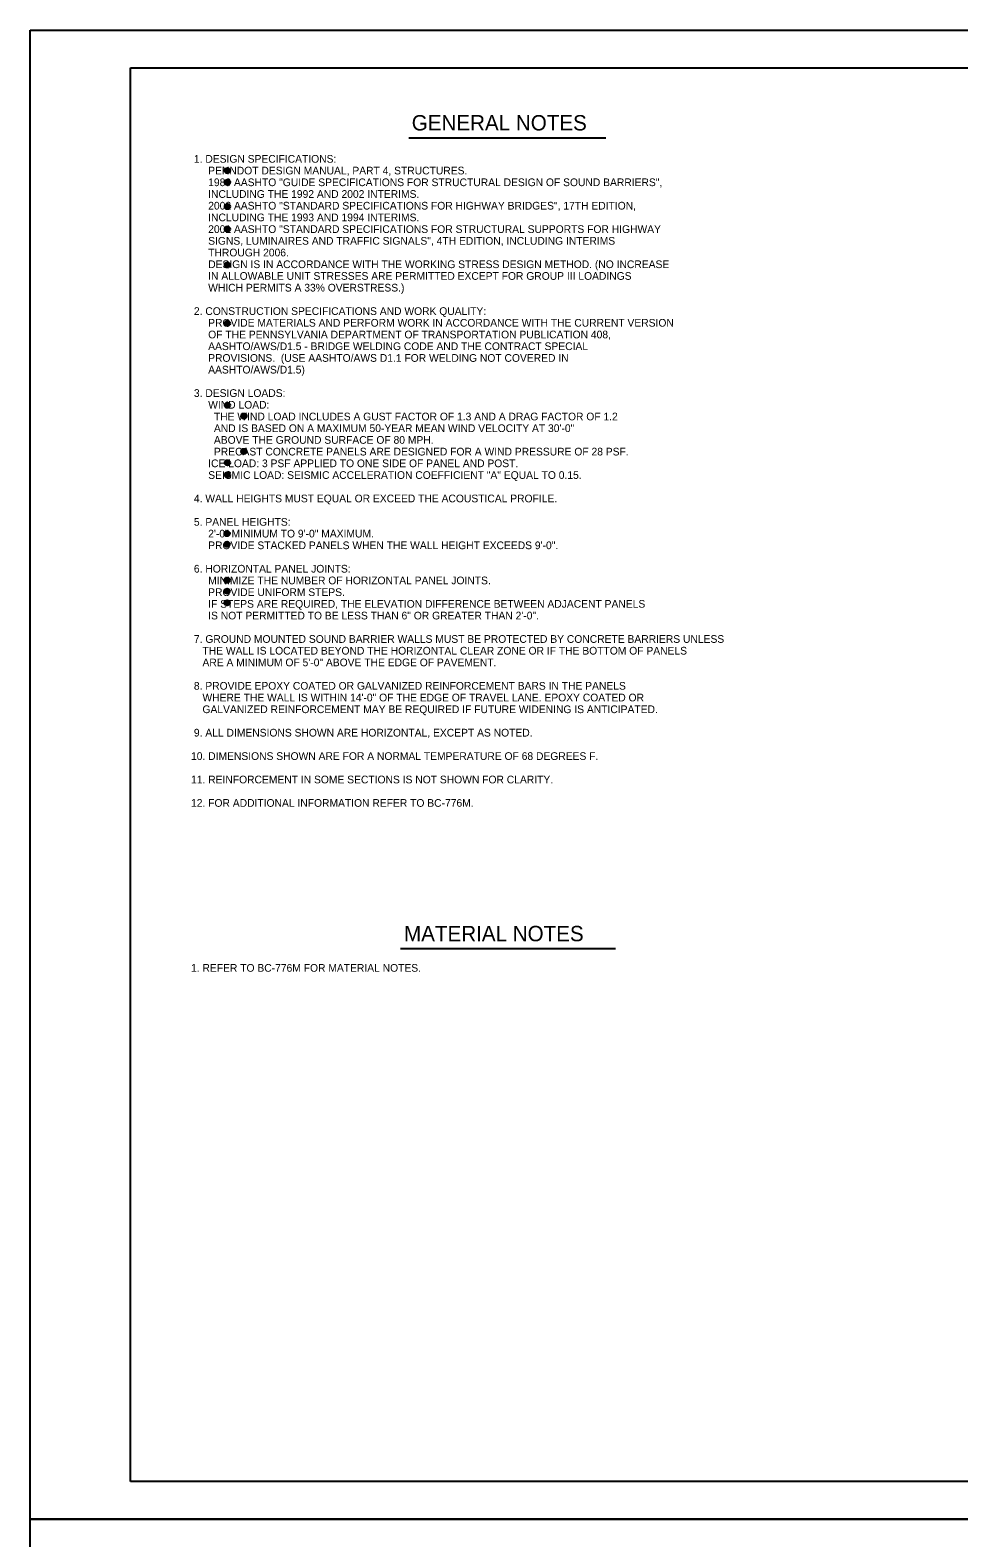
# Model space of a CAD drawing. Extents: x 3761 to 5458, y -616 to 1166.
# Drawn here: x 3761 to 4132, y 564 to 1166 of the extents above; entities that cross this region are included whole.
import ezdxf

# ---------------------------------------------------------------- set-up
doc = ezdxf.new("R2010")
doc.units = 0
for name, color, linetype in [('1', 7, 'Continuous'), ('2', 7, 'Continuous'), ('PLT-BNDY', 7, 'Continuous')]:
    doc.layers.add(name, color=color, linetype=linetype)

msp = doc.modelspace()

# ---------------------------------------------------------------- linework, layer by layer
at = {"layer": '1'}
for p, q in [((3912.43, 1122.78), (3991, 1122.78)), ((3909.14, 799.31), (3994.95, 799.31))]:
    msp.add_line(p, q, dxfattribs=at)
for centre, radius in [((3840.03, 1109.66), 1.07), ((3840.03, 1109.66), 0.8), ((3840.03, 1109.66), 0.533), ((3840.03, 1109.66), 0.267), ((3840.03, 1104.99), 1.07), ((3840.03, 1104.99), 0.8), ((3840.03, 1104.99), 0.533), ((3840.03, 1104.99), 0.267), ((3840.03, 1095.31), 1.07), ((3840.03, 1095.31), 0.8), ((3840.03, 1095.31), 0.533), ((3840.03, 1095.31), 0.267), ((3840.03, 1086.31), 1.07), ((3840.03, 1086.31), 0.8), ((3840.03, 1086.31), 0.533), ((3840.03, 1086.31), 0.267), ((3840.03, 1072.02), 1.07), ((3840.03, 1072.02), 0.8), ((3840.03, 1072.02), 0.533), ((3840.03, 1072.02), 0.267), ((3840.03, 1048.69), 1.07), ((3840.03, 1048.69), 0.8), ((3840.03, 1048.69), 0.533), ((3840.03, 1048.69), 0.267), ((3840.03, 1016.04), 1.07), ((3840.03, 1016.04), 0.8), ((3840.03, 1016.04), 0.533), ((3840.03, 1016.04), 0.267), ((3846.61, 1011.75), 1.07), ((3846.61, 1011.75), 0.8), ((3846.61, 1011.75), 0.533), ((3846.61, 1011.75), 0.267), ((3846.61, 997.62), 1.07), ((3840.03, 993.11), 1.07), ((3840.03, 993.11), 0.8), ((3840.03, 993.11), 0.533), ((3840.03, 993.11), 0.267), ((3846.61, 997.62), 0.8), ((3846.61, 997.62), 0.533), ((3846.61, 997.62), 0.267), ((3840.03, 988.26), 1.07), ((3840.03, 988.26), 0.8), ((3840.03, 988.26), 0.533), ((3840.03, 988.26), 0.267), ((3839.91, 964.82), 1.07), ((3839.91, 964.82), 0.8), ((3839.91, 964.82), 0.533), ((3839.91, 964.82), 0.267), ((3839.91, 960.59), 1.07), ((3839.91, 960.59), 0.8), ((3839.91, 960.59), 0.533), ((3839.91, 960.59), 0.267), ((3839.91, 946.25), 1.07), ((3839.91, 946.25), 0.8), ((3839.91, 946.25), 0.533), ((3839.91, 946.25), 0.267), ((3839.91, 941.88), 1.07), ((3839.91, 941.88), 0.8), ((3839.91, 941.88), 0.533), ((3839.91, 941.88), 0.267), ((3839.91, 937.21), 1.07), ((3839.91, 937.21), 0.8), ((3839.91, 937.21), 0.533), ((3839.91, 937.21), 0.267)]:
    msp.add_circle(centre, radius, dxfattribs=at)
at = {"layer": '2'}
for p, q in [((3801.34, 586.69), (3801.34, 1150.69)), ((3801.34, 1150.69), (4587.34, 1150.69)), ((4587.34, 586.69), (3801.34, 586.69))]:
    msp.add_line(p, q, dxfattribs=at)
at = {"layer": 'PLT-BNDY'}
for points in [[(3761.34, 1165.69), (4602.34, 1165.69), (4602.34, 571.69), (3761.34, 571.69)], [(3761.34, 571.69), (4602.34, 571.69), (4602.34, -22.31), (3761.34, -22.31)]]:
    msp.add_lwpolyline(points, close=True, dxfattribs=at)

# ---------------------------------------------------------------- texts
at = {"layer": '1'}
for s, height, p in [('GENERAL NOTES', 6.144, (3913.59, 1125.67)), (' 1. DESIGN SPECIFICATIONS:', 3.072, (3825.53, 1112.81)), ('      PENNDOT DESIGN MANUAL, PART 4, STRUCTURES.', 3.072, (3825.53, 1108.14)), ('      1989 AASHTO "GUIDE SPECIFICATIONS FOR STRUCTURAL DESIGN OF SOUND BARRIERS",', 3.072, (3825.53, 1103.46)), ('      INCLUDING THE 1992 AND 2002 INTERIMS.', 3.072, (3825.53, 1098.79)), ('      2002 AASHTO "STANDARD SPECIFICATIONS FOR HIGHWAY BRIDGES", 17TH EDITION, ', 3.072, (3825.53, 1094.12)), ('      INCLUDING THE 1993 AND 1994 INTERIMS.', 3.072, (3825.53, 1089.45)), ('      SIGNS, LUMINAIRES AND TRAFFIC SIGNALS", 4TH EDITION, INCLUDING INTERIMS', 3.072, (3825.53, 1080.1)), ('      2001 AASHTO "STANDARD SPECIFICATIONS FOR STRUCTURAL SUPPORTS FOR HIGHWAY', 3.072, (3825.53, 1084.78)), ('      THROUGH 2006.', 3.072, (3825.53, 1075.43)), ('      DESIGN IS IN ACCORDANCE WITH THE WORKING STRESS DESIGN METHOD. (NO INCREASE', 3.072, (3825.53, 1070.76)), ('      IN ALLOWABLE UNIT STRESSES ARE PERMITTED EXCEPT FOR GROUP III LOADINGS', 3.072, (3825.53, 1066.09)), ('      WHICH PERMITS A 33% OVERSTRESS.)', 3.072, (3825.53, 1061.42)), (' 2. CONSTRUCTION SPECIFICATIONS AND WORK QUALITY:', 3.072, (3825.53, 1052.07)), ('      PROVIDE MATERIALS AND PERFORM WORK IN ACCORDANCE WITH THE CURRENT VERSION', 3.072, (3825.53, 1047.4)), ('      AASHTO/AWS/D1.5 - BRIDGE WELDING CODE AND THE CONTRACT SPECIAL', 3.072, (3825.53, 1038.06)), ('      OF THE PENNSYLVANIA DEPARTMENT OF TRANSPORTATION PUBLICATION 408,', 3.072, (3825.53, 1042.73)), ('      PROVISIONS.  (USE AASHTO/AWS D1.1 FOR WELDING NOT COVERED IN ', 3.072, (3825.53, 1033.38)), ('      AASHTO/AWS/D1.5)', 3.072, (3825.53, 1028.71)), (' 3. DESIGN LOADS:', 3.072, (3825.53, 1019.37)), ('      WIND LOAD:', 3.072, (3825.53, 1014.7)), ('        THE WIND LOAD INCLUDES A GUST FACTOR OF 1.3 AND A DRAG FACTOR OF 1.2', 3.072, (3825.53, 1010.02)), ('        AND IS BASED ON A MAXIMUM 50-YEAR MEAN WIND VELOCITY AT 30\'-0"', 3.072, (3825.53, 1005.35)), ('        ABOVE THE GROUND SURFACE OF 80 MPH.', 3.072, (3825.53, 1000.68)), ('        PRECAST CONCRETE PANELS ARE DESIGNED FOR A WIND PRESSURE OF 28 PSF.', 3.072, (3825.53, 996.01)), ('      ICE LOAD: 3 PSF APPLIED TO ONE SIDE OF PANEL AND POST.', 3.072, (3825.53, 991.34)), ('      SEISMIC LOAD: SEISMIC ACCELERATION COEFFICIENT "A" EQUAL TO 0.15.', 3.072, (3825.53, 986.66)), (' 4. WALL HEIGHTS MUST EQUAL OR EXCEED THE ACOUSTICAL PROFILE.', 3.072, (3825.53, 977.32)), (' 5. PANEL HEIGHTS:', 3.072, (3825.53, 967.98)), ('      2\'-0" MINIMUM TO 9\'-0" MAXIMUM.', 3.072, (3825.53, 963.3)), ('      PROVIDE STACKED PANELS WHEN THE WALL HEIGHT EXCEEDS 9\'-0".', 3.072, (3825.53, 958.63)), (' 6. HORIZONTAL PANEL JOINTS:', 3.072, (3825.53, 949.29)), ('      MINIMIZE THE NUMBER OF HORIZONTAL PANEL JOINTS.', 3.072, (3825.53, 944.62)), ('      PROVIDE UNIFORM STEPS.', 3.072, (3825.53, 939.94)), ('      IF STEPS ARE REQUIRED, THE ELEVATION DIFFERENCE BETWEEN ADJACENT PANELS', 3.072, (3825.53, 935.27)), ('      IS NOT PERMITTED TO BE LESS THAN 6" OR GREATER THAN 2\'-0".', 3.072, (3825.53, 930.6)), (' 7. GROUND MOUNTED SOUND BARRIER WALLS MUST BE PROTECTED BY CONCRETE BARRIERS UNLESS', 3.072, (3825.53, 921.26)), ('    ARE A MINIMUM OF 5\'-0" ABOVE THE EDGE OF PAVEMENT.', 3.072, (3825.53, 911.91)), ('    THE WALL IS LOCATED BEYOND THE HORIZONTAL CLEAR ZONE OR IF THE BOTTOM OF PANELS', 3.072, (3825.53, 916.58)), (' 8. PROVIDE EPOXY COATED OR GALVANIZED REINFORCEMENT BARS IN THE PANELS', 3.072, (3825.53, 902.57)), ('    WHERE THE WALL IS WITHIN 14\'-0" OF THE EDGE OF TRAVEL LANE. EPOXY COATED OR ', 3.072, (3825.53, 897.9)), ('    GALVANIZED REINFORCEMENT MAY BE REQUIRED IF FUTURE WIDENING IS ANTICIPATED.', 3.072, (3825.53, 893.22)), (' 9. ALL DIMENSIONS SHOWN ARE HORIZONTAL, EXCEPT AS NOTED.', 3.072, (3825.53, 883.88)), ('10. DIMENSIONS SHOWN ARE FOR A NORMAL TEMPERATURE OF 68 DEGREES F.', 3.072, (3825.53, 874.54)), ('11. REINFORCEMENT IN SOME SECTIONS IS NOT SHOWN FOR CLARITY.', 3.072, (3825.53, 865.19)), ('12. FOR ADDITIONAL INFORMATION REFER TO BC-776M.', 3.072, (3825.53, 855.85)), ('MATERIAL NOTES', 6.144, (3910.52, 802.2)), ('1. REFER TO BC-776M FOR MATERIAL NOTES. ', 3.072, (3825.53, 790.04))]:
    msp.add_text(s, height=height, dxfattribs=at).set_placement(p)

doc.saveas('drawing.dxf')
